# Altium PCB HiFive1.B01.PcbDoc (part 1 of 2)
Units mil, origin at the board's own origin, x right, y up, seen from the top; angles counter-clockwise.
Board outline 2700 x 2100 mil, 2 copper layers (Top Layer, Bottom Layer), stack 61 mil thick; 112 components, 78 nets, 451 pads, 247 vias.
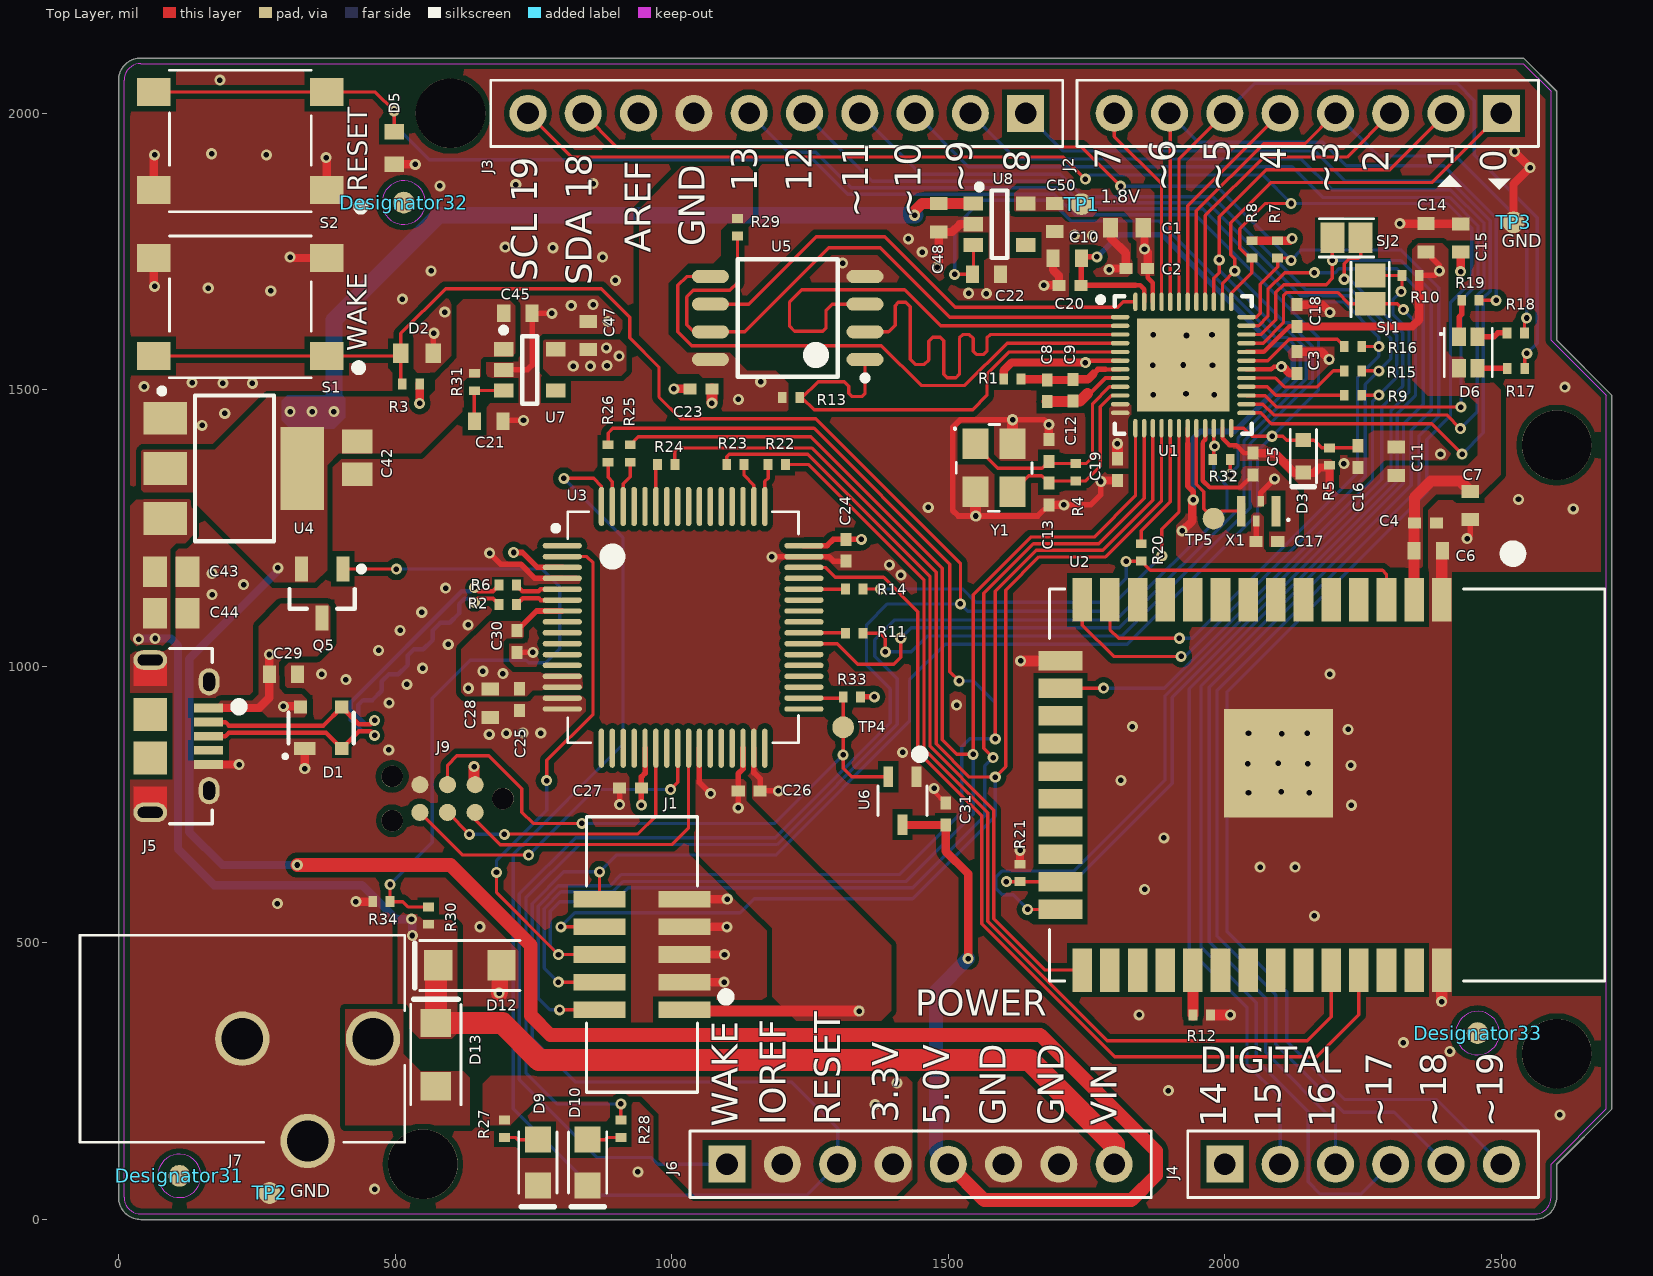
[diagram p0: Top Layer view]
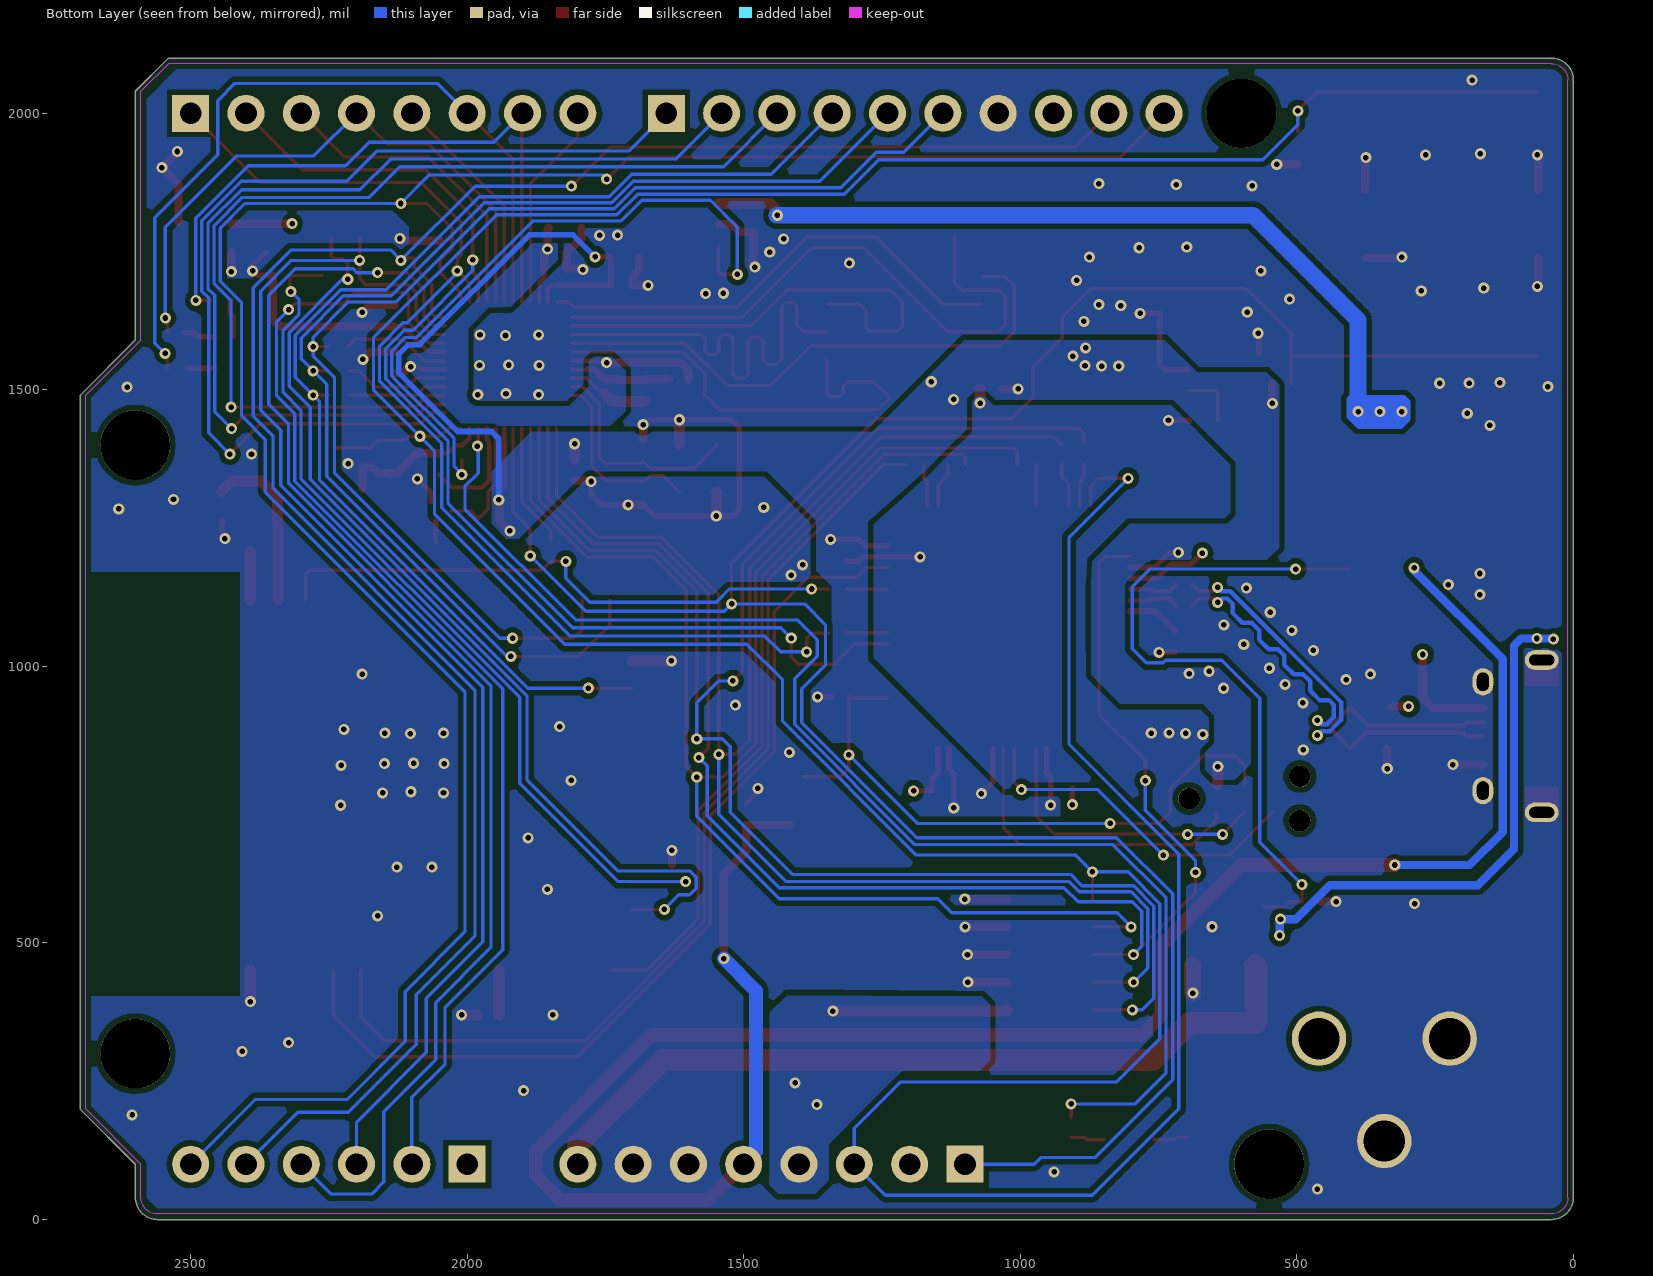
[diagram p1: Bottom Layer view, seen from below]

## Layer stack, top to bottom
Top Solder: solder mask 0.5, Solder Resist, Dk 3.5
Top Layer: signal copper 1.4
Dielectric 1: core 58.2, FR-4, Dk 4
Bottom Layer: signal copper 1.4
Bottom Solder: solder mask 0.5, Solder Resist, Dk 3.5

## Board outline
0,40 0,2060 cw(c40,2060) 40,2100 2540,2100 2600,2040 2600,1590 2700,1490 2700,200 2600,100 2600,40 cw(c2560,40) 2560,0 40,0 cw(c40,40)

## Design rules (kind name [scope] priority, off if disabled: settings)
Clearance 90ohm [InNetClass('DIFF90') vs IsRegion] p1: gap=6 ignorepadtopadclearanceinfootprint=FALSE except(5: Track-Track SMDPad-SMDPad SMDPad-Poly SMDPad-Region Region-Region; 7: Via-Poly; 8: Arc-Hole Track-Hole SMDPad-Hole THPad-Hole Via-Hole Fill-Hole Poly-Hole Region-Hole Text-Hole; 10: Arc-Poly THPad-Poly Fill-Poly; 12: Poly-Poly)
Clearance PolygonClearance [InPolygon] p2: gap=10 ignorepadtopadclearanceinfootprint=FALSE except(8: Arc-Hole Track-Hole SMDPad-Hole THPad-Hole Via-Hole Fill-Hole Poly-Hole Region-Hole Text-Hole)
Clearance [All] p3: gap=6 ignorepadtopadclearanceinfootprint=FALSE except(5: Track-Track SMDPad-SMDPad SMDPad-Poly SMDPad-Region Region-Region; 8: Arc-Hole Track-Hole SMDPad-Hole THPad-Hole Via-Hole Fill-Hole Poly-Hole Region-Hole Text-Hole; 10: Arc-Poly THPad-Poly Via-Poly Fill-Poly; 12: Track-Poly Poly-Poly)
ComponentClearance [All] p1: gap=3 collisioncheckmode=3 verticalgap=3 showdistances=FALSE
DiffPairsRouting DIFF90DiffPairsRouting [InNetClass('DIFF90')] p1: maxlimit=5 minlimit=5 mostfreqgap=5 toplayer_minwidth=8 toplayer_maxwidth=8 toplayer_prefwidth=8 bottomlayer_minwidth=8 bottomlayer_maxwidth=8 bottomlayer_prefwidth=8 maxuncoupledlength=500
HoleSize [All] p1: absolutevalues=TRUE maxlimit=150 minlimit=1 maxpercent=80.000 minpercent=20.000
MatchedLengths QSPIMatchedLengths [InNetClass('QSPI')] p1: tolerance=200 checknetsindiffpair=FALSE checkdiffpairvsdiffpair=TRUE checkxsignals=TRUE checkothers=TRUE
MatchedLengths Diff90MatchedLengths [InxSignalClass('USB')] p2: tolerance=10 checknetsindiffpair=TRUE checkdiffpairvsdiffpair=FALSE checkxsignals=FALSE checkothers=FALSE
MinimumSolderMaskSliver [All] p1: minsoldermaskwidth=0
PlaneClearance [All] p1: clearance=10
PlaneConnect [All] p1: planeconnectstyle=Direct reliefexpansion=20 reliefentries=4 reliefconductorwidth=10 reliefairgap=10
PolygonConnect [All] p1: connectstyle=Direct reliefconductorwidth=10 reliefentries=4 polygonreliefangle="90 Angle" airgapwidth=10
RoutingVias [All] p1: holewidth=10 width=20 viastyle="Through Hole" minholewidth=10 minwidth=20 maxholewidth=28 maxwidth=50
SilkToSilkClearance [All] p1: silktosilkclearance=0
SilkToSolderMaskClearance [IsPad] p1: minsilkscreentomaskgap=0 clearancetoexposedcopper=TRUE
SolderMaskExpansion [All] p1: expansion=4
Width PWR [InNetClass('PWR')] p1: maxlimit=40 minlimit=8 preferedwidth=20 minimp=50.000000 maximp=50.000000 favimp=50.000000
Width AntennaImpedanceMatch [(InNet('ANT_OUT1') OR InNet('ANT_OUT2') OR InNet('LNA_IN'))] p2: maxlimit=6.32 minlimit=5.42 preferedwidth=6.08 impedancedriven=TRUE minimp=49.000000 maximp=53.000000 favimp=50.000000
Width [All] p3: maxlimit=40 minlimit=6 preferedwidth=6
22 further rules are at their usual default settings.

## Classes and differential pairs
component class Freedom_E310: C1 C2 C3 C5 C7 C8 C9 C10 C11 C12 C13 C14 C15 C16 C17 C18 C19 C20 C23 D2 D3 D5 D6 J1 J2 J3 J4 J6 R1 R3 R4 R5 R7 R8 R9 R10 R13 R15 R16 R17 R18 R19 R29 S1 S2 SJ1 SJ2 TP5 U1 U5 X1 Y1
component class Debug: C24 C25 C26 C27 C28 C29 C30 C31 D1 J5 J9 R2 R6 R11 R14 R22 R23 R24 R25 R26 R33 TP4 U3 U6
component class Power: C21 C22 C42 C43 C44 C45 C47 C48 C50 D9 D10 D12 D13 J7 Q5 R27 R28 R30 R31 R32 R34 TP1 TP2 TP3 U4 U7 U8
net class DIFF90: USB_D_N USB_D_P USB_D_R_N USB_D_R_P
component class WiFi_BT: C4 C6 R12 R20 R21 U2
net class QSPI: QSPI_CS0 QSPI_DQ0 QSPI_DQ1 QSPI_DQ2 QSPI_DQ3 QSPI_SCK
differential pair USB_D_R: +USB_D_R_P -USB_D_R_N
differential pair USB_D: +USB_D_P -USB_D_N

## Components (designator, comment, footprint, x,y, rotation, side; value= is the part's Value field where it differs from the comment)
C1 "10uF" C0603#1 1823,1793 r180 top
C2 "0.1uF" C0402#1 1840.83,1719.37 r0 top
C3 "0.1uF" C0402#2 2130.83,1549.37 r270 top
C4 "0.1uF" C0402#1 2362.87,1259.1 r180 top
C5 "0.1uF" C0402#1 2051,1366 r90 top
C6 "10uF" C0603#2 2367.87,1209.1 r0 top
C7 "10uF" C0603#2 2444,1291 r270 top
C8 "0.1uF" C0402#3 1678.99,1498.37 r90 top
C9 "0.1uF" C0402#3 1725.83,1499.37 r90 top
C10 "10uF" C0603#2 1715,1738 r180 top
C11 "10uF" C0603#2 2310,1371 r90 top
C12 "15pF" C0402#1 1681.83,1390.53 r90 top
C13 "15pF" C0402#1 1681.83,1311.79 r270 top
C14 "10uF" C0603#2 2363.8,1775 r90 top
C15 "10uF" C0603#2 2426.52,1774.66 r90 top
C16 "10nF" C0402#1 2240.83,1379.37 r270 top
C17 "0.1uF" C0402#1 2076,1226 r180 top
C18 "0.1uF" C0402#1 2130.83,1634.37 r270 top
C19 "0.1uF" C0402#1 1805.83,1355.86 r90 top
C20 "0.1uF" C0402#1 1720,1689 r0 top
C21 "DNP" C0603#2 669,1443 r0 top value=10uF
C22 "10uF" C0603#2 1569.17,1708.88 r0 top
C23 "0.1uF" C0402#1 1052.76,1501.93 r180 top
C24 "0.1uF" C0402#1 1315,1210 r270 top
C25 "0.1uF" C0402#1 725,940 r270 top locked
C26 "0.1uF" C0402#1 1140,775 r0 top
C27 "0.1uF" C0402#1 925.32,780 r180 top
C28 "10uF" C0603#2 671.82,933.34 r90 top
C29 "10uF" C0603#2 298,986 r180 top
C30 "0.1uF" C0402#1 720,1045 r270 top
C31 "0.1uF" C0402#1 1495.46,733.1 r90 top
C42 "22uF" C0805 431,1377 r270 top
C43 "10uF" C0805 95,1171 r0 top
C44 "10uF" C0805 95,1096 r0 top
C45 "1uF" C0603#2 721.87,1638.21 r0 top
C47 "1uF" C0603#2 848.74,1598.27 r90 top
C48 "1uF" C0603#2 1482.63,1811.13 r270 top
C50 "1uF" C0603#2 1692.47,1811.75 r270 top
D1 "PRTR5V0U2X,215" SOT-143B 366.05,888.93 r0 top
D2 "PESD0603-240" R0603 539.53,1566 r0 top
D3 "Diode" SOD523 2142,1380 r90 top value=1N4148WT-7
D5 "PESD0603-240" R0603 498.06,1937.39 r270 top
D6 "LED_RGB_LTST-C19HE1WT" LED0606 2440.27,1567.54 r270 top value=RGB
D9 "Green" LED0805 758,103 r90 top
D10 "Green" LED0805 848,103 r90 top
D12 "SMF12A" SOD-123FL 635,459.37 r0 top
D13 "DB2W40300L" SOD-123FL 573.58,298.1 r270 top
Designator31 "Comment" FIDUCIAL10-20 110,79 r180 top
Designator32 "Comment" FIDUCIAL10-20 515.62,1838.64 r180 top
Designator33 "Comment" FIDUCIAL10-20 2457,337 r180 top
J1 "JTAG" CNC_3221-10-0300-00 1023.11,379.12 r90 top locked
J2 "Arduino_8P_IO" ARDUINO_8P_IO 2150,2000 r180 top locked
J3 "Arduino_10P" ARDUINO_10P 1190,2000 r180 top locked
J4 "Arduino_6P" ARDUINO_6P 2250,100 r0 top locked
J5 "MicroUSB2.0 Connector" FCI_10118194-0001LF 162.5,925 r270 top locked
J6 "Arduino_8P_POWER" ARDUINO_8P_POWER 1450,100 r0 top locked
J7 "PowerJack3P" PJ-102AH 204,327 r0 top locked
J9 "Header 2x3" TC2030-IDC-FP 594.65,761.11 r180 top
Q5 "MOSFET-P_SOT23" SOT-23B 368,1132 r270 top value=P-Channel
R1 "100R" R0402 1615.83,1519.37 r0 top
R2 "33R" R0402 703.63,1111.89 r0 top
R3 "100K" R0402 528.53,1511 r180 top
R4 "1M" R0402 1730.45,1351.16 r270 top
R5 "100K" R0402 2189.32,1379.37 r270 top
R6 "33R" R0402 703.63,1146.89 r0 top
R7 "DNP" R0402 2095.51,1754.06 r90 top value=2K
R8 "DNP" R0402 2049.01,1754.06 r90 top value=2K
R9 "22R" R0402 2231.83,1490.37 r180 top
R10 "100K" R0402 2336,1706.96 r0 top
R11 "100R" R0402 1330,1060 r0 top
R12 "1K" R0402 1958.34,370.01 r180 top
R13 "100K" R0402 1215.76,1485.93 r180 top
R14 "100R" R0402 1330,1140 r0 top
R15 "22R" R0402 2231.83,1534.37 r180 top
R16 "22R" R0402 2231.83,1578.37 r180 top
R17 "330R" R0402 2526.54,1539 r0 top
R18 "330R" R0402 2526,1603 r0 top
R19 "330R" R0402 2444,1662 r0 top
R20 "1K" R0402 1849,1206.31 r90 top
R21 "DNP" R0402 1629.6,626.85 r270 top value=1K
R22 "100R" R0402 1190,1365 r0 top locked
R23 "100R" R0402 1115,1365 r180 top
R24 "100R" R0402 990,1365 r0 top
R25 "100R" R0402 925,1385 r90 top
R26 "100R" R0402 885,1385 r90 top
R27 "330R" R0402 698,164.02 r270 top
R28 "330R" R0402 908,164.02 r270 top
R29 "100K" R0402 1119,1794 r270 top
R30 "100K" R0402 560,549.37 r270 top
R31 "100K" R0402 643.18,1514.41 r90 top
R32 "150K" R0402 1994,1374 r0 top
R33 "100K" R0402 1325.75,945 r180 top
R34 "100K" R0402 475,574.69 r0 top
S1 "SW-PB 4P" PTS645_SMT 220,1650 r180 top locked
S2 "SW-PB 4P" PTS645_SMT 220,1950 r180 top locked
SJ1 "Solder Jumper" SJ0805 2262.83,1681.37 r90 top
SJ2 "Solder Jumper" SJ0805 2220,1775 r0 top
TP1 "Testpoint" TESTPOINT_SMT 1740.93,1835.72 r270 top
TP2 "Testpoint" TESTPOINT_SMT 273,48 r270 top
TP3 "Testpoint" TESTPOINT_SMT 2522,1803 r270 top
TP4 "Testpoint" TESTPOINT_SMT 1310,890 r90 top
TP5 "Testpoint" TESTPOINT_SMT 1979.74,1267.16 r90 top
U1 "FE310-G002" QFN48_40P600X600X90_HS-49 1925,1545 r0 top locked
U2 "ESP32-SOLO-1" ESP-WROOM-32 2061.17,785.63 r270 top
U3 "MK22FN128VLH10" LQFP-64 1020.63,1070.71 r0 top locked
U4 "NCP1117LPST50T3G" SOT223P700X180-4N 208,1358 r0 top locked
U5 "32Mbit" SOIC127P790X216-8N 1209.76,1630 r180 top locked
U6 "MIC803-30D2VC3" SOT65P210X110-3N_A 1417.21,757.33 r180 top locked
U7 "RT9080-33GJ5" TSOT23-5 743.36,1536.17 r0 top
U8 "RT9080-18GJ5" TSOT23-5 1592.72,1799.4 r0 top locked
X1 "32.768KHz" SiTime2012 2061,1281 r180 top locked
Y1 "16MHz" X3225 1583,1359 r270 top

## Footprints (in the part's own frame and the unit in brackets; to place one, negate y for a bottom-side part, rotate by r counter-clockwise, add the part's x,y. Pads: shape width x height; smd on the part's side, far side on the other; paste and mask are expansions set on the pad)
ARDUINO_6P [mm] "Arduino 6 Pin Header; Pitch 2.54 mm (0.100 in); 1x6"
  rect 1.7x1.7 hole 1: 1(-6.35,0)
  round 1.7 hole 1: 2(-3.81,0) 3(-1.27,0) 4(1.27,0) 5(3.81,0) 6(6.35,0)
  silkscreen extent -8.05,-1.52 8.05,1.52, body extent -8.12,-1.59 8.12,1.59, height 20.6
ARDUINO_8P_IO [mm] "Arduino 8 Pin IO Header; Pitch 2.54 mm (0.100 in); 1x8"
  rect 1.7x1.7 hole 1: 1(-8.89,0)
  round 1.7 hole 1: 2(-6.35,0) 3(-3.81,0) 4(-1.27,0) 5(1.27,0) 6(3.81,0) 7(6.35,0) 8(8.89,0)
  silkscreen extent -10.59,-1.52 10.59,3.5, body extent -10.66,-1.59 10.66,3.5, height 20.6
ARDUINO_8P_POWER [mm] "Arduino 8 Pin Power Header; Pitch 2.54 mm (0.100 in); 1x8"
  rect 1.7x1.7 hole 1: 1(-8.89,0)
  round 1.7 hole 1: 2(-6.35,0) 3(-3.81,0) 4(-1.27,0) 5(1.27,0) 6(3.81,0) 7(6.35,0) 8(8.89,0)
  silkscreen extent -10.59,-1.52 10.59,1.52, body extent -10.66,-1.59 10.66,1.59, height 20.6
ARDUINO_10P [mm] "Arduino 10 Pin Header; Pitch 2.54 mm (0.100 in); 1x10"
  rect 1.7x1.7 hole 1: 1(-11.43,0)
  round 1.7 hole 1: 2(-8.89,0) 3(-6.35,0) 4(-3.81,0) 5(-1.27,0) 6(1.27,0) 7(3.81,0) 8(6.35,0) 9(8.89,0) 10(11.43,0)
  silkscreen extent -13.13,-1.52 13.13,1.52, body extent -13.2,-1.59 13.2,1.59, height 20.6
C0402#1 [mm] "Chip Capacitor, Body 1.0x0.5mm, IPC High Density"
  rect 0.6x0.5 smd: 1(-0.5,0) 2(0.5,0)
  body extent -0.95,-0.4 0.95,0.4, height 1.3
C0402#2 [mm] "Chip Capacitor, Body 1.0x0.5mm, IPC High Density"
  rect 0.6x0.5 smd: 1(-0.5,0)
  rect 0.6x0.5 smd mask+0.038: 2(0.5,0)
  body extent -0.95,-0.4 0.95,0.4, height 1.3
C0402#3 [mm] "Chip Capacitor, Body 1.0x0.5mm, IPC High Density"
  rect 0.6x0.5 smd mask+0.038: 1(-0.5,0)
  rect 0.6x0.5 smd: 2(0.5,0)
  body extent -0.95,-0.4 0.95,0.4, height 1.3
C0603#1 [mm] "Chip Capacitor, Body 1.6x0.8mm, IPC High Density"
  rect 0.7x0.9 smd: 1(-0.75,0) 2(0.75,0)
  body extent -1.25,-0.6 1.25,0.6, height 0.9
C0603#2 [mm] "Chip Capacitor, Body 1.6x0.8mm, IPC High Density"
  rect 0.6x0.8 smd mask+0.05: 1(-0.65,0) 2(0.65,0)
  body extent -1,-0.53 1.06,0.53, height 0.9
C0805 [mm] "Chip Capacitor, Body 2.0x1.3mm, IPC High Density"
  rect 1.1x1.4 smd: 1(-0.75,0) 2(0.75,0)
  body extent -1.45,-0.85 1.45,0.85, height 1.4
CNC_3221-10-0300-00 [mm]
  rect 0.76x2.4 smd mask+0: 1(0,0) 2(0,3.9) 3(1.27,0) 4(1.27,3.9) 5(2.54,0) 6(2.54,3.9) 7(3.81,0) 8(3.81,3.9) 9(5.08,0) 10(5.08,3.9)
  silkscreen extent -3.78,-2.1 8.86,4.5, body extent -5.13,-2.52 10.21,6.42, height 5.6
ESP-WROOM-32 [mm] "Espressif WiFi / BT Module"
  rect 2x0.9 smd: 1(-8.5,8.41) 2(-8.5,7.14) 3(-8.5,5.87) 4(-8.5,4.6) 5(-8.5,3.33) 6(-8.5,2.06) 7(-8.5,0.79) 8(-8.5,-0.48) 9(-8.5,-1.75) 10(-8.5,-3.02) 11(-8.5,-4.29) 12(-8.5,-5.56) 13(-8.5,-6.83) 14(-8.5,-8.1) 25(8.5,-8.1) 26(8.5,-6.83) 27(8.5,-5.56) 28(8.5,-4.29) 29(8.5,-3.02) 30(8.5,-1.75) 31(8.5,-0.48) 32(8.5,0.79) 33(8.5,2.06) 34(8.5,3.33) 35(8.5,4.6) 36(8.5,5.87) 37(8.5,7.14) 38(8.5,8.41)
  rect 0.9x2 smd: 15(-5.715,-9.1) 16(-4.445,-9.1) 17(-3.175,-9.1) 18(-1.905,-9.1) 19(-0.635,-9.1) 20(0.635,-9.1) 21(1.905,-9.1) 22(3.175,-9.1) 23(4.445,-9.1) 24(5.715,-9.1)
  rect 5x5 smd paste-2.5 mask+0: 39(-1,0.91)
  rect 1.75x1.75 on Top Paste: ""(-2.125,2.035) ""(-2.125,-0.215) ""(0.125,2.035) ""(0.125,-0.215)
  silkscreen extent -10.94,-9.6 9,15.9, body extent -11.24,-10.2 9.6,15.96, height 1.27
FCI_10118194-0001LF [mm] "CONN RCPT USB2.0 MICRO B SMD R/A"
  rect 0.4x1.35 smd mask+0: 1(0,0) 2(0.65,0) 3(1.3,0) 4(1.95,0) 5(2.6,0)
  oval 1.25x0.95 hole 0.55 slot 0.85 at 0 deg paste+0 mask+0: SH1(-1.2,0.025) SH2(3.8,0.025)
  oval 0.9x1.55 hole 0.5 slot 1.15 at 90 deg mask+0: SH3(-2.2,-2.675) SH6(4.8,-2.675)
  rect 1.5x1.55 smd mask+0: SH4(0.3,-2.675) SH5(2.3,-2.675)
  Top Layer region: -2.2,-3.45 -1,-3.45 -1,-1.9 -2.2,-1.9
  Top Layer region: 3.6,-3.45 4.8,-3.45 4.8,-1.9 3.6,-1.9
  silkscreen extent -2.73,-1.78 5.33,1.6, body extent -8.22,-9.48 7.32,1.99, height 3
FIDUCIAL10-20 [mm]
  round 1 smd paste-1 mask+0.5: 1(0,0)
  body extent -1,-1 1,1, height 1.27
LED0606 [mm] "LED 4 PIN 0606"
  rect 0.85x0.65 smd mask+0.041: 1(-0.725,-0.425) 2(-0.725,0.425) 3(0.725,0.425) 4(0.725,-0.425)
  silkscreen extent -1.1,-1.3 1.1,1.1, body extent -1.19,-1.35 1.19,1.16, height 0.35
LED0805 [mm] "Chip LED, Body 2.0x1.2mm, IPC High Density"
  rect 1.2x1.2 smd: 1(-1.05,0) 2(1.05,0)
  silkscreen extent -2.03,-0.88 1.4,0.88, body extent -2.16,-0.94 1.75,0.94, height 0.9
LQFP-64 [mm] "Thin QFP, 64-Leads, Body 10x10mm, Pitch 0.5mm, IPC Medium Density"
  oval 1.8x0.25 smd mask+0.07: 1(-5.55,3.75) 2(-5.55,3.25) 3(-5.55,2.75) 4(-5.55,2.25) 5(-5.55,1.75) 6(-5.55,1.25) 7(-5.55,0.75) 8(-5.55,0.25) 9(-5.55,-0.25) 10(-5.55,-0.75) 11(-5.55,-1.25) 12(-5.55,-1.75) 13(-5.55,-2.25) 14(-5.55,-2.75) 15(-5.55,-3.25) 16(-5.55,-3.75) 33(5.55,-3.75) 34(5.55,-3.25) 35(5.55,-2.75) 36(5.55,-2.25) 37(5.55,-1.75) 38(5.55,-1.25) 39(5.55,-0.75) 40(5.55,-0.25) 41(5.55,0.25) 42(5.55,0.75) 43(5.55,1.25) 44(5.55,1.75) 45(5.55,2.25) 46(5.55,2.75) 47(5.55,3.25) 48(5.55,3.75)
  oval 0.25x1.8 smd mask+0.07: 17(-3.75,-5.55) 18(-3.25,-5.55) 19(-2.75,-5.55) 20(-2.25,-5.55) 21(-1.75,-5.55) 22(-1.25,-5.55) 23(-0.75,-5.55) 24(-0.25,-5.55) 25(0.25,-5.55) 26(0.75,-5.55) 27(1.25,-5.55) 28(1.75,-5.55) 29(2.25,-5.55) 30(2.75,-5.55) 31(3.25,-5.55) 32(3.75,-5.55) 49(3.75,5.55) 50(3.25,5.55) 51(2.75,5.55) 52(2.25,5.55) 53(1.75,5.55) 54(1.25,5.55) 55(0.75,5.55) 56(0.25,5.55) 57(-0.25,5.55) 58(-0.75,5.55) 59(-1.25,5.55) 60(-1.75,5.55) 61(-2.25,5.55) 62(-2.75,5.55) 63(-3.25,5.55) 64(-3.75,5.55)
  silkscreen extent -5.97,-5.3 5.3,5.3, body extent -6.72,-6.72 6.73,6.73, height 1.6
PJ-102AH [mm] "PJ-102AH DC Jack"
  round 2.5 hole 1.9: 1(6.5,0) 2(0.5,0) 3(3.5,-4.7)
  silkscreen extent -6.95,-4.75 7.95,4.75, body extent -7.25,-6.05 8.02,4.82, height 11
PTS645_SMT [mm] "Pushbutton SPST SMT"
  rect 1.55x1.3 smd: 1(-3.975,2.25) 2(3.975,2.25) 3(-3.975,-2.25) 4(3.975,-2.25)
  silkscreen extent -3.25,-3.25 3.25,3.25, body extent -4.9,-3.32 4.9,3.32, height 4.4
QFN48_40P600X600X90_HS-49 [mm] "QFN, 48-Leads, Body 6.00x6.00mm, Pitch 0.40mm, Thermal Pad 4.25x4.25mm, IPC Medium Density"
  oval 0.85x0.2 smd paste+0 mask+0.05: 1(-2.9,2.2)
  oval 0.85x0.2 smd mask+0.05: 2(-2.9,1.8) 3(-2.9,1.4) 4(-2.9,1) 5(-2.9,0.6) 6(-2.9,0.2) 7(-2.9,-0.2) 8(-2.9,-0.6) 9(-2.9,-1) 10(-2.9,-1.4) 11(-2.9,-1.8) 12(-2.9,-2.2) 25(2.9,-2.2) 26(2.9,-1.8) 27(2.9,-1.4) 28(2.9,-1) 29(2.9,-0.6) 30(2.9,-0.2) 31(2.9,0.2) 32(2.9,0.6) 33(2.9,1) 34(2.9,1.4) 35(2.9,1.8) 36(2.9,2.2)
  oval 0.2x0.85 smd mask+0.05: 13(-2.2,-2.9) 14(-1.8,-2.9) 15(-1.4,-2.9) 16(-1,-2.9) 17(-0.6,-2.9) 18(-0.2,-2.9) 19(0.2,-2.9) 20(0.6,-2.9) 21(1,-2.9) 22(1.4,-2.9) 23(1.8,-2.9) 24(2.2,-2.9) 37(2.2,2.9) 38(1.8,2.9) 39(1.4,2.9) 40(1,2.9) 41(0.6,2.9) 42(0.2,2.9) 43(-0.2,2.9) 44(-0.6,2.9) 45(-1,2.9) 46(-1.4,2.9) 47(-1.8,2.9) 48(-2.2,2.9)
  rect 4.25x4.25 smd paste-2.125 mask+0.05: 49(0,0)
  rect 1.375x1.375 on Top Paste mask+0: ""(-0.937,-0.937) ""(-0.937,0.937) ""(0.937,-0.937) ""(0.937,0.937)
  silkscreen extent -3.92,-3.15 3.15,3.15, body extent -4.05,-3.6 3.6,3.6, height 0.9
R0402 [mm] "Chip Resistor, Body 1.0x0.5mm, IPC High Density"
  rect 0.4x0.5 smd mask+0.05: 1(-0.4,0) 2(0.4,0)
  body extent -0.65,-0.35 0.65,0.35, height 1.3
R0603 [mm] "Chip Resistor, Body 1.6x0.8mm, IPC High Density"
  rect 0.7x0.9 smd: 1(-0.75,0) 2(0.75,0)
  body extent -1.25,-0.6 1.25,0.6, height 0.9
SiTime2012 [mm] "SiTime 2.0mmx1.2mm Oscillator Package"
  rect 0.4x1.4 smd: 1(-0.8,0) 3(0.8,0)
  rect 0.3x0.5 smd: 2(-0.1,-0.45) 4(0.1,0.45)
  silkscreen extent -1.42,0.36 -1.32,0.46, body extent -1.47,-0.9 1.3,0.9, height 0.6
SJ0805 [mm] "Solder Bridge, Body 2.0x1.3mm, IPC High Density"
  rect 1.1x1.4 smd mask+0.102: 1(-0.65,0)
  rect 1.1x1.4 smd paste+0: 2(0.65,0)
  silkscreen extent -1.25,-0.88 1.25,0.88, body extent -1.31,-0.94 1.32,0.94, height 1.27
SOD523 [mm] "SOD523, 2-Leads, Body 0.80x1.60mm, IPC Medium Density"
  rect 0.65x0.7 smd: 1(-0.75,0) 2(0.75,0)
  silkscreen extent -1.4,-0.6 1.22,0.6, body extent -1.52,-0.66 1.29,0.66, height 0.65
SOD-123FL [mm]
  rect 1.3x1.4 smd: 1(-1.45,0) 2(1.45,0)
  silkscreen extent -2.54,-1.15 2.3,1.15, body extent -2.67,-1.21 2.36,1.21, height 1.1
SOIC127P790X216-8N [mm] "SOIC, 8-Leads, Body 5.28x5.28mm, Pitch 1.27mm, IPC Medium Density"
  oval 1.7x0.6 smd: 1(-3.55,1.905) 2(-3.55,0.635) 3(-3.55,-0.635) 4(-3.55,-1.905) 5(3.55,-1.905) 6(3.55,-0.635) 7(3.55,0.635) 8(3.55,1.905)
  silkscreen extent -3.68,-2.7 2.3,2.88, body extent -4.67,-2.97 4.67,3.01, height 2.16
SOT65P210X110-3N_A [mm]
  rect 0.45x0.95 smd mask+0: 1(-0.65,-1.1) 2(0.65,-1.1) 3(0,1.1)
  silkscreen extent -1.12,-2.33 1.12,0.67, body extent -1.45,-2.84 1.45,1.87, height 1.1
SOT223P700X180-4N [mm] "SOT223, 4-Leads, Body 6.50x7.00mm (avg), Pitch 2.30mm, IPC Medium Density"
  rect 2x1.5 smd mask+0.05: 1(-3.15,2.3) 2(-3.15,0) 3(-3.15,-2.3)
  rect 2x3.8 smd mask+0.05: 4(3.15,0)
  silkscreen extent -3.43,-3.35 1.85,3.68, body extent -4.27,-3.62 4.28,3.81, height 1.8
SOT-23B [mm] "SOT23, 3-Leads, Body 2.9x1.3mm, Pitch 0.95mm, Lead Span 2.4mm, IPC Medium Density"
  rect 1.15x0.6 smd: 1(-1.125,0.95) 2(-1.125,-0.95) 3(1.125,0)
  silkscreen extent -1.25,-1.5 0.7,1.93, body extent -2,-1.8 2,2.05, height 1.2
SOT-143B [mm]
  rect 1x0.6 smd: 1(-0.75,-0.95)
  rect 0.6x0.6 smd: 2(0.95,-0.95) 3(0.95,0.95) 4(-0.95,0.95)
  silkscreen extent -1.72,-1.38 1.5,0.7, body extent -1.82,-1.48 1.6,1.35, height 1.27
TC2030-IDC-FP [mil] "Tag Connect 6 Pin Connector"
  round 31 smd paste-30 mask+1.18: 1(-50,-25) 2(-50,25) 3(0,-25) 4(0,25) 5(50,-25) 6(50,25)
  round 39 hole 39 unplated paste+0 mask+0: SH1(-100,0) SH2(100,40) SH3(100,-40)
  body extent -123,-62 124,63, height 50
TESTPOINT_SMT [mm]
  round 1 smd paste-1 mask+0: 1(0,0)
  body extent -0.5,-0.5 0.5,0.5, height 1.27
TSOT23-5 [mm] "SOT23, 6-Leads, Thin Body 2.9x1.6mm, Pitch 0.95mm, Lead Span 2.7mm, IPC High Density"
  rect 0.9x0.65 smd: 1(-1.2,0.95) 2(-1.2,0) 3(-1.2,-0.95) 4(1.2,-0.95) 5(1.2,0.95)
  silkscreen extent -1.32,-1.55 0.35,1.95, body extent -1.8,-1.7 1.8,2.08, height 1.1
X3225 [mm] "Crystal 3.2mmx2.5mm"
  rect 1.4x1.2 smd mask+0.07: 1(-1.1,-0.85) 2(1.1,-0.85) 3(1.1,0.85) 4(-1.1,0.85)
  silkscreen extent -2,-1.85 2,1.74, body extent -2.06,-1.9 2.06,1.81, height 0.8

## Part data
C1 C6 C7 C10 C11 C14 C15 C22 C28 C29: library part C0100033, "CAP CER 10UF 10V X5R 0603", Manufacturer="Murata Electronics", Manufacturer PN=GRM188R61A106KE69J, Operating Temperature="-55°C ~ 85°C", Tolerance=±10%, Voltage Rating=10V
C2 C3 C4 C5 C8 C9 C17 C18 C19 C20 C23 C24 C25 C26 C27 C30 C31: library part C0100004, "0.10µF 16V Ceramic Capacitor X7R 0402", Manufacturer="Samsung Electro-Mechanics", Manufacturer PN=CL05B104KO5NFNC, Operating Temperature="-55°C ~ 125°C", Tolerance=±10%, Voltage Rating=16V
C12 C13: library part C0100038, "CAP CER 15PF 50V C0G/NPO 0402", Manufacturer=Yageo, Manufacturer PN=CC0402JRNPO9BN150, Operating Temperature="-55°C ~ 125°C", Tolerance=±5%, Voltage Rating=50V
C16: library part C0100037, "CAP CER 10000PF 50V X7R 0402", Manufacturer="Samsung Electro-Mechanics", Manufacturer PN=CL05B103KB5VPNC, Operating Temperature="-55°C ~ 125°C", Tolerance=±10%, Voltage Rating=50V
C21: library part C0100007, "10µF 6.3V Ceramic Capacitor X5R 0603", Manufacturer="Murata Electronics", Manufacturer PN=GRM188R60J106ME47J, Operating Temperature="-55°C ~ 85°C", Tolerance=±10%, Voltage Rating=6.3V
C42: library part C0100010, "22µF 6.3V Ceramic Capacitor X5R 0805", Manufacturer="Murata Electronics", Manufacturer PN=GRM21BR60J226ME39L, Operating Temperature="-55°C ~ 85°C", Tolerance=±20%, Voltage Rating=6.3V
C43 C44: library part C0100015, "10µF ±10% 25V Ceramic Capacitor X5R 0805", Manufacturer="Murata Electronics", Manufacturer PN=GRM21BR61E106KA73L, Operating Temperature="-55°C ~85°C", Tolerance=±10%, Voltage Rating=25V
C45 C47 C48 C50: library part C0100006, "1µF 16V Ceramic Capacitor X5R 0603", Manufacturer="Murata Electronics", Manufacturer PN=GRM188R61C105KA93D, Operating Temperature="-55°C ~ 85°C", Tolerance=±10%, Voltage Rating=16V
D1: library part D0000012, "TVS DIODE 5.5V SOT143B", Manufacturer=Nexperia, Temperature Range="-40°C ~ 85°C", Voltage Breakdown=6V, Voltage Reverse Standoff=5.5V
D2 D5: library part D0000013, "TVS Diode 24VWM  45VClamp", Manufacturer=Littlefuse, Temperature Range="-55°C ~ 125°C", Voltage Reverse Standoff=24V
D3: library part D0000001, "Diode Standard 80V 125mA Surface Mount SOD-523", Manufacturer="Diodes Incorporated", Manufacturer PN=1N4148WT-7, Temperature Range="-65°C ~ 150°C"
D6: library part E0000005, "Red, Green, Blue (RGB) 624nm Red, 525nm Green, 470nm Blue LED Indication - Discrete 1.8V Red, 2.8V Green, 2.8V Blue 0606", Manufacturer="Lite-on Inc.", Manufacturer PN=LTST-C19HE1WT, Temperature Range="-20°C ~ 80°C", Voltage Forward="1.8V Red, 2.8V Green, 2.8V Blue"
D9 D10: library part E0000001, "Green 570nm LED Indication - Discrete 2.2V 0805", Manufacturer="OSRAM Opto Semiconductors Inc", Manufacturer PN="LG R971-KN-1", Temperature Range="-65°C ~ 150°C", Voltage Forward=2.2V
D12: library part D0000002, "TVS DIODE 12VWM 19.9VC SOD123", Manufacturer="Littelfuse Inc", Temperature Range="-55°C ~ 150°C", Voltage Breakdown=13.3V, Voltage Reverse Clamping=19.9V, Voltage Reverse Standoff=12V
D13: library part D0000006, "Diode Schottky 40V 3A (DC) Surface Mount", Manufacturer="Panasonic Electronic Components", Temperature Range="-65°C ~ 150°C", Voltage Forward=0.54V@3A
J1: library part J0000049, "Connector Header Surface Mount 10 position 0.050\" (1.27mm)", Manufacturer="CNC Tech", Manufacturer PN=3221-10-0300-00
J2: library part J0000005, "Arduino 8 Pin I/O Connector", Manufacturer="Sullins Connector Solutions", Manufacturer PN=PPTC081LFBN-RC
J3: library part J0000007, "Arduino 10 Pin Connector", Manufacturer="Sullins Connector Solutions", Manufacturer PN=PPTC101LFBN-RC
J4: library part J0000004, "Arduino 6 Pin Connector", Manufacturer="Sullins Connector Solutions", Manufacturer PN=PPTC061LFBN-RC
J5: library part J0000048, "USB - micro B USB 2.0 Receptacle Connector 5 Position Surface Mount, Right Angle, Horizontal", Manufacturer="Amphenol FCI", Manufacturer PN=10118194-0001LF
J6: library part J0000006, "Arduino 8 Pin Power Connector", Manufacturer="Sullins Connector Solutions", Manufacturer PN=PPTC081LFBN-RC
J7: library part J0000003, "Power Barrel Connector Jack 2.00mm ID (0.079\"), 5.50mm OD (0.217\") Through Hole, Right Angle", Manufacturer="CUI Inc", Manufacturer PN=PJ-102AH
J9: library part J0000045, "2x3 Connector, Small footprint, no legs, no component", Manufacturer="Tag Connect", Manufacturer PN=TC2030-IDC-FP
Q5: library part Q0000005, "MOSFET P-CH 20V 4.2A SOT23", Manufacturer="Diodes Inc", Manufacturer PN=DMG2305UX-13, Temperature Range="-55°C ~ 150°C"
R1 R11 R14 R22 R23 R24 R25 R26: library part R0000020, "RES SMD 100 OHM 1% 1/16W 0402", Manufacturer=Yageo, Manufacturer PN=RC0402FR-07100RL, Power Rating=0.063W, Temperature Range="-55°C ~ 155°C", Tolerance=±1%
R2 R6: library part R0000044, "RES SMD 33 OHM 1% 1/16W 0402", Manufacturer=Yageo, Manufacturer PN=RC0402FR-0733RL, Power Rating=0.063W, Temperature Range="-55°C ~ 155°C", Tolerance=±1%
R3 R5 R10 R13 R29 R30 R31 R33 R34: library part R0000012, "RES SMD 100K OHM 1% 1/16W 0402", Manufacturer=Yageo, Manufacturer PN=RC0402FR-07100KL, Power Rating=0.063W, Temperature Range="-55°C ~ 155°C", Tolerance=±1%
R4: library part R0000021, "RES SMD 1M OHM 1% 1/16W 0402", Manufacturer=Yageo, Manufacturer PN=RC0402FR-071ML, Power Rating=0.063W, Temperature Range="-55°C ~ 155°C", Tolerance=±1%
R7 R8: library part R0000025, "RES SMD 2K OHM 1% 1/16W 0402", Manufacturer=Yageo, Manufacturer PN=RC0402FR-072KL, Power Rating=0.063W, Temperature Range="-55°C ~ 155°C", Tolerance=±1%
R9 R15 R16: library part R0000022, "RES SMD 22 OHM 1% 1/16W 0402", Manufacturer=Yageo, Manufacturer PN=RC0402FR-0722RL, Power Rating=0.063W, Temperature Range="-55°C ~ 155°C", Tolerance=±1%
R12 R20 R21: library part R0000019, "RES SMD 1K OHM 1% 1/16W 0402", Manufacturer=Yageo, Manufacturer PN=RC0402FR-071KL, Power Rating=0.063W, Temperature Range="-55°C ~ 155°C", Tolerance=±1%
R17 R18 R19 R27 R28: library part R0000026, "RES SMD 330 OHM 1% 1/16W 0402", Manufacturer=Yageo, Manufacturer PN=RC0402FR-07330RL, Power Rating=0.063W, Temperature Range="-55°C ~ 155°C", Tolerance=±1%
R32: library part R0000055, "RES SMD 150K OHM 1% 1/16W 0402", Manufacturer=Yageo, Manufacturer PN=RC0402FR-07150KL, Power Rating=0.063W, Temperature Range="-55°C ~ 155°C", Tolerance=±1%
S1: library part M0000004, "Blue Tactile Switch SPST-NO Top Actuated Surface Mount", Manufacturer="C & K Components", Manufacturer PN="PTS645SM43SMTR92 LFS"
S2: library part M0000003, "Red Tactile Switch SPST-NO Top Actuated Surface Mount", Manufacturer="C & K Components", Manufacturer PN="PTS645SK43SMTR92 LFS"
SJ1 SJ2: library part M0000009, "Solder Bridge 0805", Manufacturer=None
TP1 TP2 TP3 TP4 TP5: library part M0000002, "Test Point SMT"
U1: library part U0000050, "SiFive Freedom E310 Microcontroller", Manufacturer=SiFive, Temperature Range="-40°C ~ 85°C"
U2: library part U0000061, "WiFi 802.11n + BT4.2 Chipset Module Single Core with PCB Antenna 18mmx25.5mm", Manufacturer="Espressif Systems", Temperature Range="-40°C ~ 85°C"
U3: library part U0000058, "ARM® Cortex®-M4 Kinetis K20 Microcontroller IC 32-Bit 100MHz 128KB (128K x 8) FLASH 64-LQFP (10x10)", Manufacturer="NXP USA Inc", Temperature Range="-40°C ~ 105°C"
U4: library part U0000051, "IC REG LINEAR 5V 1A SOT223", Manufacturer="ON Semiconductor", Temperature Range="-0°C ~ 125°C"
U5: library part U0000019, "IC FLASH 32MBIT 133MHZ 8SOIC 2.3 V ~ 3.6 V", Manufacturer=ISSI, Manufacturer PN=IS25LP032D-JBLE, Temperature Range="-40°C ~ 105°C"
U6: library part U0000076, "IC MPU SUPERVISOR SC70-3", Manufacturer=Microchip, Temperature Range="-40°C ~ 125°C"
U7: library part U0000066, "Linear Voltage Regulator IC Positive Fixed 1 Output 3.3V 600mA TSOT-23-5", Manufacturer="Richtek USA", Temperature Range="-40°C ~ 85°C"
U8: library part U0000065, "Linear Voltage Regulator IC Positive Fixed 1 Output 1.8V 600mA TSOT-23-5", Manufacturer="Richtek USA", Temperature Range="-40°C ~ 85°C"
X1: library part X0000014, "32.768kHz LVCMOS MEMS (Silicon) Oscillator Surface Mount 1.2 V ~ 3.63 V 1.3µA", Frequency Stability="±100 ppm", Manufacturer=SiTime, Manufacturer PN=SIT1533AI-H4-DCC-32.768E, Temperature Range="-40°C ~ 85°C"
Y1: library part X0000015, "16MHz ±10ppm Crystal 9pF 60 Ohm", Frequency Stability=±18ppm, Frequency Tolerance=±10ppm, Load Capacitance=9pF, Manufacturer=Epson, Manufacturer PN="TSX-3225 16.0000MF18X-AC0", Temperature Range="-40°C ~ 85°C"

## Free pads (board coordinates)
  round 125.98 hole 125.98 unplated paste-0.98 mask+2.76: Mech1(550,100)
  round 125.98 hole 125.98 unplated paste+0 mask+0: Mech2(600,2000) Mech3(2600,1400) Mech4(2600,300)

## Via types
v1: diameter 20, hole 10, Top Layer to Bottom Layer, tented both sides, 229 vias
v2: diameter 20, hole 10.1, Top Layer to Bottom Layer, tented both sides, 18 vias

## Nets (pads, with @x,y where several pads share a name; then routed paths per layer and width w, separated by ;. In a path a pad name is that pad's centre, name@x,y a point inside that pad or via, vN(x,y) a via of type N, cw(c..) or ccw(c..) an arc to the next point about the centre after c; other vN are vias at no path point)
DBG_RST: J9.3 R33.2 TP4.1 U3.34 U6.2 | length 1173.4
  Top Layer w6: J9.3@594.65,786.11 594.65,821.55 611.58,838.48 669.29,838.48 729,778.76 729,736.6 749.48,716.12 v1(837.4,716.12) ; U3.34@1239.13,942.76 1307.76,942.76 R33.2@1310,945 TP4.1@1310,890 v1(1310,840) 1310,815.81 1325.18,800.63 U6.2@1391.62,800.63
  Bottom Layer w6: v1(837.4,716.12) 1186.12,716.12 v1(1310,840)
DBG_SWDCLK: J9.4 U3.22 | length 529.5
  Top Layer w6: J9.4@594.65,736.11 v1(634.26,696.5) ; v1(697.5,696.5) 698.12,697.12 939.04,697.12 971.42,729.5 U3.22@971.42,852.2
  Bottom Layer w6: v1(634.26,696.5) v1(697.5,696.5)
DBG_SWDIO: J9.2 U3.25 | length 574.7
  Top Layer w6: J9.2@644.65,736.11 644.65,722.48 689.63,677.5 733.07,677.5 733.49,677.92 1000.07,677.92 1030.47,708.32 U3.25@1030.47,852.2
DBG_SWO: J9.6 U3.24 | length 614.4
  Top Layer w6: J9.6@544.65,736.11 621.85,658.92 v1(741.36,658.92) ; v1(997.84,777.34) 1010.79,790.29 U3.24@1010.79,852.2
  Bottom Layer w6: v1(741.36,658.92) 859.78,777.34 v1(997.84,777.34)
DBG_TGT_TCK: R25.1 U3.62 | length 81.3
  Top Layer w6: U3.62@912.36,1289.21 912.36,1330.36 925,1343 R25.1@925,1365.32
DBG_TGT_TDI: R24.1 U3.59 | length 76.2
  Top Layer w6: R24.1@970.32,1365 971.42,1363.9 U3.59@971.42,1289.21
DBG_TGT_TMS: R26.1 U3.63 | length 79.3
  Top Layer w6: R26.1@885,1365.32 885,1342 892.68,1334.32 U3.63@892.68,1289.21
DBG_UART1_DTR: R23.1 U3.50 | length 83.2
  Top Layer w6: R23.1@1130.75,1365 1130.75,1345.73 1148.58,1327.9 U3.50@1148.58,1289.21
DBG_UART1_RTS: R14.1 U3.44 | length 75.3
  Top Layer w6: U3.44@1239.13,1139.61 1313.86,1139.61 R14.1@1314.25,1140
DBG_UART1_TX: R22.1 U3.49 | length 78.3
  Top Layer w6: U3.49@1168.27,1289.21 1168.27,1334.45 1174.25,1340.43 R22.1@1174.25,1365
DBG_UART_TX: R11.1 U3.40 | length 75.5
  Top Layer w6: U3.40@1239.13,1060.87 1313.39,1060.87 R11.1@1314.25,1060
DCIN_DET: Q5.1 R30.1 R34.2 | length 1263.6
  Top Layer w6: Q5.1@405.4,1176.29 405.69,1176 v1(502,1176) ; R34.2@490.75,574.69 v1(490.75,605.75) v1@494.69,609.69 ; R34.2@494.69,574.69 513.57,574.69 523.14,565.12 R30.1@560,565.12
  Bottom Layer w6: v1(490.75,605.75) 567.01,682.01 567.01,942.43 635.65,1011.07 736.58,1011.07 741.08,1006.57 772.26,1006.57 797.72,1032.03 797.72,1144.41 766.14,1176 v1(502,1176)
GND: C1.2 C2.1 C3.1 C4.1 C5.1 C6.2 C7.2 C10.2 C11.2 C12.2 C13.2 C14.2 C15.2 C16.2 C17.1 C18.1 C19.1 C20.1 C21.2 C22.2 C23.1 C24.2 C25.2 C26.2 C27.2 C28.1 C29.1 C30.2 C31.2 C42.2 C43.2 C44.2 C45.2 C47.2 C48.2 C50.2 D1.1 D2.2 D5.2 D9.1 D10.1 D12.2 J1.3 J1.5 J1.7 J1.9 J3.7 J5.5 J5.SH1 J5.SH2 J5.SH3 J5.SH6 J6.6 J6.7 J7.2 J7.3 J9.5 R12.1 R21.1 R34.1 S1.3 S1.4 S2.1 S2.2 TP2.1 TP3.1 U1.21 U1.49 U2.1 U2.15 U2.38 U2.39 U3.4 U3.15 U3.16 U3.31 U3.47 U4.1 U5.4 U6.1 U7.2 U8.2 X1.2 Y1.2 Y1.4 | length 3606.9
  Top Layer w8: v1(1474.31,779.49) 1474.31,773.93 C31.2@1495.46,752.78 ; U1.21@1964.37,1430.83 1964.37,1409.65 1960.62,1405.91 1960.62,1404.03 1960.38,1403.79 1960.38,1335.94 1972.84,1323.48 2028.16,1323.48 C5.1@2051,1346.32 ; C7.2@2438,1259.41 C7.2@2444,1265.41
  Top Layer w10: D2.2@569.06,1566 569.06,1597.47 570.06,1598.47 v1(570.06,1602.44) ; v1(670.64,1204.99) 690.63,1185 727,1185 752.71,1159.29 U3.4@802.13,1159.29 ; C21.2@694.59,1443 696.59,1445 v1(732,1445) ; U7.2@696.11,1536.17 738.68,1536.17 747.46,1544.95 C45.2@747.46,1638.21 v1(783.31,1638.21) ; C30.2@720,1025.31 720.25,1025.57 v1(748.95,1025.57) ; v1(905.63,750.31) C27.2@905.63,780 ; U3.31@1148.58,852.2 1148.58,808.18 1159.69,797.08 C26.2@1159.69,775 v1(1192.94,775) ; v1(1181.12,1198.24) 1181.54,1198.66 U3.47@1239.13,1198.66 1284.05,1198.66 1292.39,1190.31 C24.2@1315,1190.31 ; C13.2@1681.83,1292.1 1661.72,1272 v1(1549.69,1272) 1518.44,1272 1508.15,1282.29 1508.15,1432.13 1522.02,1446 v1(1616.31,1446) 1673.12,1446 v1(1681.83,1437.29) ; v1(1708.9,1292.1) 1757.19,1292.1 1775.83,1310.74 v1(1775.83,1334.37) ; X1.2@2064.94,1298.72 2064.94,1313.94 v1(2090,1339) ; v1(2438,1231) 2444,1237 C7.2@2444,1265.41
  Top Layer w15: S1.4@63.5,1738.58 63.5,1688.5 v1(65,1687.01) ; S2.2@63.5,1861.42 63.5,1923.5 v1(65,1925) ; J5.5@162.5,822.64 v1(217.86,822.64) ; v1(310,1740) 311.42,1738.58 S1.3@376.5,1738.58 ; v1(336.53,815.37) D1.1@336.53,851.53 ; v1(375,1920) 376.5,1918.5 S2.1@376.5,1861.42 ; v1(429,574.69) R34.1@455.32,574.69 ; D5.2@498.06,1907.87 v1(536.32,1907.87) ; J1.3@1023.11,429.12 v1(1094.66,429.12) ; J1.5@1023.11,479.12 v1(1095.41,479.12) ; J1.7@1023.11,529.12 v1(1099.56,529.12) ; J1.9@1023.11,579.12 v1(1100.45,579.12) ; v1(1480,1722) 1482.63,1724.63 C48.2@1482.63,1785.54 1507.11,1785.54 1520.97,1799.4 U8.2@1545.48,1799.4 ; R21.1@1629.6,642.6 1629.6,666.96 v1(1630.05,667.41) ; v1(1673,1689) C20.1@1700.32,1689 1700.31,1706.24 1689.41,1717.15 C10.2@1689.41,1738 ; C13.2@1681.83,1292.1 v1(1708.9,1292.1) ; C12.2@1681.83,1410.22 v1(1681.83,1437.29) ; v1(1775.83,1334.37) 1777.63,1336.17 C19.1@1805.83,1336.17 ; v1(1790.97,1717.52) 1792.82,1719.37 C2.1@1821.14,1719.37 1821.14,1747.06 1793.47,1774.72 C1.2@1793.47,1793 ; C3.1@2130.83,1569.05 2174.39,1569.05 v1(2188.47,1554.98) ; C18.1@2130.83,1654.06 2175.94,1654.06 v1(2190,1640) ; v1(2316.67,1800.59) C14.2@2363.8,1800.59 2364.14,1800.25 C15.2@2426.52,1800.25 ; TP3.1@2522,1803 2522,1872 v1(2552,1902) 2524,1930 v1(2524,1931)
  Top Layer w20: v1(1072.45,1476) C23.1@1072.45,1501.93 ; Y1.2@1549.54,1315.69 1549.54,1272.15 v1(1549.69,1272) ; v1(1616.31,1446) 1616.46,1445.85 Y1.4@1616.46,1402.31 ; v1(1631,1010) U2.15@1702.28,1010 ; R12.1@1981.65,370 v1(2010,370) ; v1(2392,394) 2392.28,394.28 U2.38@2392.28,450.98 ; U2.1@2392.28,1120.28 C6.2@2392.28,1207.92
  Top Layer w30: v1(688,409.37) 689.4,410.77 D12.2@689.4,459.37
  other v1: 463,55 939,86 2606,189 1898,233 2407,304 2323,320 1845,370 653,529.37 2162,549 287,571 1855,597 2064,637 2127,637 1890,690 2229,749 1812,794 2228,821 1417.31,844.63 488.42,849.27 670.1,877.3 701.14,878.78 730.96,880.03 763.24,879.53 2223,886 1833,891 1515,930 489.2,934.12 521.27,967.48 411,976 367,986 2190,986 549.68,996.7 470,1029 596,1040 509,1065 632,1075 548,1098 169,1130 591.36,1141.51 226,1148 1414.45,1165.12 169,1168 1393.53,1183.43 2630,1285 1463.83,1287.57 2531,1302 2215.49,1366.85 2390,1384 151,1436 191.91,1457.41 2615,1505 46,1506 188.59,1512.14 242,1512 133,1513 885,1624 589.67,1640.53 818.34,1652.41 858,1654 513,1664 1568.86,1674 1536.86,1674.7 275,1679 162,1684 898,1698 565,1715 1308.97,1729.38 875,1740 1453,1749 785,1757 699,1758 1428,1773 1760.47,1779.49 1728,1779.92 581,1869 718,1871 858,1873 267,1925 168,1927 183,2060
  other v2: 2042.83,771.37 2152.83,771.37 2101.83,773.37 2041.83,824.37 2149.83,824.37 2097,825 2102.83,878.37 2042.83,879.37 2148.83,879.37 1870.83,1491.37 1980.83,1491.37 1929.83,1493.37 1869.83,1544.37 1977.83,1544.37 1925,1545 1930.83,1598.37 1870.83,1599.37 1976.83,1599.37
GPIO_0: J3.1 U1.25 | length 1783.5
  Top Layer w6: U1.25@2039.17,1458.39 2064.92,1458.39 2084.3,1439 2374,1439 v1(2429,1384)
  Bottom Layer w6: J3.1@1640,2000 1708.23,1931.77 2163.23,1931.77 2218,1877 2408.44,1877 2479.69,1805.76 2479.69,1678.61 2467.52,1666.44 2467.52,1422.52 v1(2429,1384)
GPIO_1: J3.2 U1.26 | length 1805
  Top Layer w6: U1.26@2039.17,1474.13 2068.97,1474.13 2088.43,1454.67 2401.33,1454.67 v1(2426,1430)
  Bottom Layer w6: J3.2@1540,2000 1622.56,1917.44 2138.56,1917.44 2194,1862 2407.89,1862 2468.69,1801.2 2468.69,1683.16 2456.52,1671 2456.52,1460.52 v1(2426,1430)
GPIO_2: J3.3 U1.27 | length 1847.9
  Top Layer w6: J3.3@1440,2000 J3.3@1446.5,1993.5 ; U1.27@2039.17,1489.88 2039.69,1489.37 2073.53,1489.37 2093.9,1469 v1(2427,1469)
  Bottom Layer w6: J3.3@1440,2000 1536.56,1903.44 2121.56,1903.44 2177,1848 2406.33,1848 2457.69,1796.65 2457.69,1691.71 2427,1661.02 v1(2427,1469)
GPIO_3: R9.2 U1.28 | length 179.3
  Top Layer w6: U1.28@2039.17,1505.63 2077.07,1505.63 2092.33,1490.37 R9.2@2212.14,1490.37
GPIO_4: R15.2 U1.29 | length 191.6
  Top Layer w6: U1.29@2039.17,1521.38 2091.82,1521.38 2107.83,1505.37 2167.38,1505.37 2196.38,1534.37 R15.2@2212.14,1534.37
GPIO_5: R16.2 U1.31 | length 198.2
  Top Layer w6: U1.31@2039.17,1552.87 2078.07,1552.87 2116.57,1591.37 2203.08,1591.37 R16.2@2216.08,1578.37
GPIO_9: J4.2 SJ1.1 U1.33 | length 2154.9
  Top Layer w6: U1.33@2039.17,1584.37 2069.37,1584.37 2106.05,1621.05 2106.05,1670.45 2111.71,1676.12 2203.88,1676.12 2224.22,1655.78 SJ1.1@2262.84,1655.78 2312.22,1655.78 v1(2323,1645)
  Bottom Layer w6: J4.2@2100,100 2100,221 2040,281 2040,384 1936,488 1936,959.33 2311.51,1334.84 2311.51,1456.51 2344.78,1489.78 2344.78,1623.22 v1(2323,1645)
GPIO_10: J4.3 SJ2.1 U1.34 | length 2340.5
  Top Layer w6: U1.34@2039.17,1600.12 2065.32,1600.12 2092.05,1626.85 2092.05,1676.25 2106.17,1690.37 2183.37,1690.37 2194.41,1701.41 v1(2194.41,1734) SJ2.1@2194.41,1774.99
  Bottom Layer w6: v1(2194.41,1734) 2317.7,1734 2373.08,1678.62 2373.08,1463.08 2337,1427 2337,1327.8 1972,962.8 1972,502 2074,400 2074,302 2200,176 J4.3@2200,100
GPIO_11: J4.4 U1.35 | length 2451.4
  Top Layer w6: U1.35@2039.17,1615.87 2060.96,1615.87 2078.05,1632.96 2078.05,1682.05 2108,1712 v1(2162,1712) ; J4.4@2290,100 J4.4@2300,100
  Bottom Layer w6: v1(2162,1712) 2199.28,1712 2206.28,1719 2311,1719 2358.78,1671.22 2358.78,1473.78 2323,1438 2323,1330.77 1957,964.77 1957,492 2057,392 2057,289 2151,195 2151,68 2173,46 2246,46 J4.4@2300,100
GPIO_12: J3.9 J4.5 R7.1 U1.36 | length 3835
  Top Layer w6: J3.9@840,2000 901,1939 1741.15,1939 v1(1811.77,1868.38) ; U1.36@2039.17,1631.61 2056.91,1631.61 2064.05,1638.76 2064.05,1691.43 2095.51,1722.89 R7.1@2095.51,1738.31 2115.8,1738.31 v1@2119.74,1734.37
  Bottom Layer w6: v1(1811.77,1868.38) 1985.73,1868.38 v1(2119.88,1734.23) 2138.65,1753 2318.5,1753 2387.08,1684.42 2387.08,1452.08 2351,1416 2351,1322 1986,957 1986,512 2092,406 2092,317 2215,194 2306,194 J4.5@2400,100
GPIO_13: J3.10 J4.6 R8.1 U1.37 | length 4245.8
  Top Layer w6: J3.10@740,2000 819,1921 1708,1921 v1(1748,1881) ; U1.37@2011.61,1659.17 2011.61,1674.61 2049.01,1712.01 2049.01,1734.37 2027,1756.38 2027,1791 2073,1837 v1(2120,1837)
  Bottom Layer w6: v1(1748,1881) 1755.66,1888.66 2068.34,1888.66 v1(2120,1837) 2401.77,1837 2446.69,1792.09 2446.69,1696.27 2408,1657.58 2408,1453 2365,1410 2365,1315 2004,954 2004,520 2112,412 2112,322 2217,217 2383,217 J4.6@2500,100
GPIO_16: J2.1 R11.2 U1.38 | length 2099.8
  Top Layer w6: R11.2@1345.75,1060 1377.29,1060 1386.22,1051.06 v1(1386.22,1026.36) ; U1.38@1995.87,1659.17 1995.87,1692.87 v1(2018,1715) 2018,1737 2011,1744 2011,1802 2084,1875 2375,1875 J2.1@2500,2000
  Bottom Layer w6: v1(1386.22,1026.36) 1433.26,1026.36 1461.9,1055 1814.1,1055 2045.75,1286.65 2045.75,1403.07 2158.47,1515.79 2158.47,1579.19 2116.22,1621.44 2108.56,1621.44 2018,1712 v1(2018,1715)
GPIO_17: J2.2 U1.39 U3.39 | length 2158.8
  Top Layer w6: U3.39@1239.13,1041.18 1299.03,1041.18 1336.34,1003.88 1401.67,1003.88 1414.05,1016.26 v1(1414.05,1051.25) ; U1.39@1980.12,1659.17 1980.12,1702.12 1990,1712 v1(1990,1735) 1990,1813 2075,1898 2298,1898 J2.2@2400,2000
  Bottom Layer w6: v1@1414.05,1051 1433.05,1070 1809.3,1070 2034.75,1295.45 2034.75,1407.62 2147.47,1520.34 2147.47,1574.63 2114.03,1608.06 2097.84,1608.06 1990,1715.91 v1(1990,1735)
GPIO_18: J2.3 U1.40 | length 568.3
  Top Layer w6: U1.40@1964.37,1659.17 1964.37,1815.37 2070,1921 2221,1921 J2.3@2300,2000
